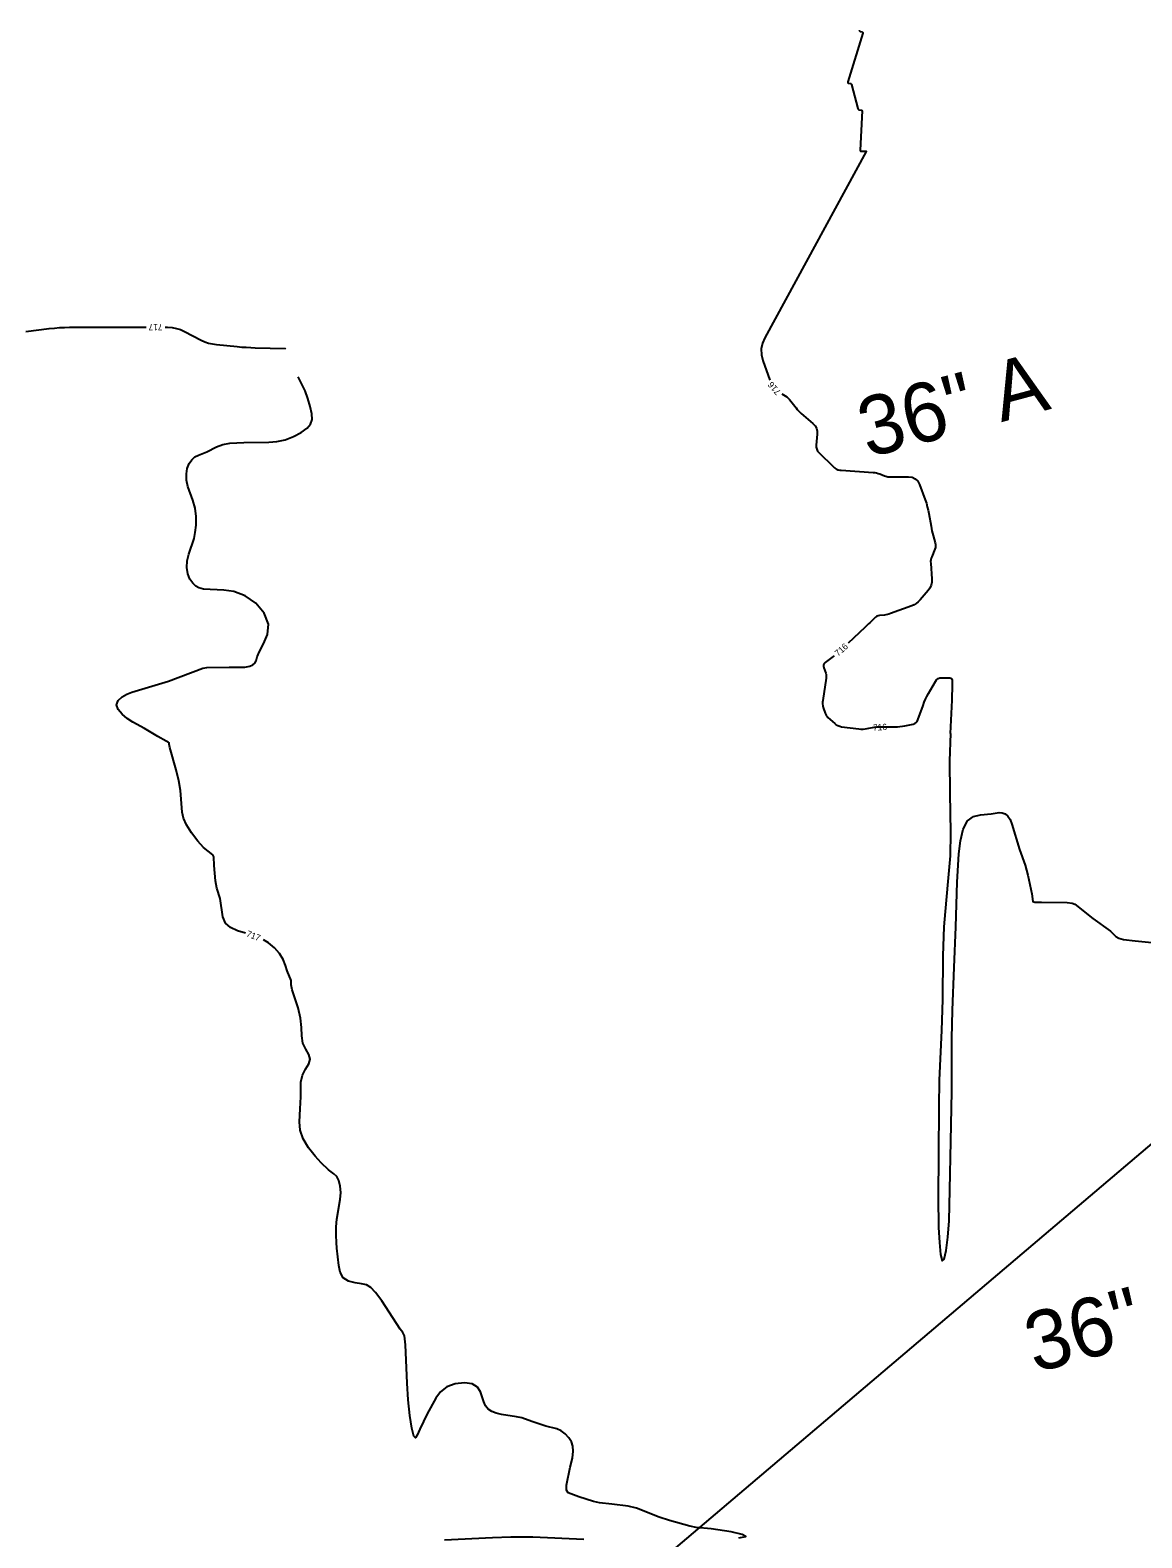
# Model space of a CAD drawing. Extents: x -361782338 to 28259792, y -263199453 to 8342113.
# Drawn here: x 1402889 to 1403593, y 576397 to 577352 of the extents above; entities that cross this region are included whole.
import ezdxf

# ---------------------------------------------------------------- set-up
doc = ezdxf.new("R2010")
doc.units = 0
for name, color, linetype in [('DT_X_Contour_Minor', 7, 'Continuous'), ('Level 19', 7, 'Continuous'), ('Level 40', 7, 'Continuous')]:
    doc.layers.add(name, color=color, linetype=linetype)

msp = doc.modelspace()

# ---------------------------------------------------------------- linework, layer by layer
at = {"layer": 'DT_X_Contour_Minor'}
for points in [[(1403413.63, 577351.77), (1403413.63, 577351.58), (1403413.74, 577351.3), (1403413.95, 577351.09), (1403414.28, 577350.95), (1403415.52, 577350.62), (1403415.74, 577350.53), (1403415.88, 577350.38), (1403415.93, 577350.19), (1403415.89, 577349.95), (1403406.42, 577318.97), (1403406.37, 577318.66), (1403406.44, 577318.41), (1403406.63, 577318.25), (1403406.94, 577318.16), (1403408.15, 577317.99), (1403408.38, 577317.93), (1403408.57, 577317.81), (1403408.7, 577317.64), (1403408.79, 577317.42), (1403412.77, 577302.05), (1403412.9, 577301.73), (1403413.1, 577301.49), (1403413.36, 577301.34), (1403413.7, 577301.27), (1403414.91, 577301.18), (1403415.13, 577301.13), (1403415.29, 577301.02), (1403415.38, 577300.85), (1403415.4, 577300.62), (1403414.2, 577275.76), (1403414.23, 577275.45), (1403414.35, 577275.23), (1403414.56, 577275.11), (1403414.87, 577275.07), (1403416.02, 577275.1), (1403416.26, 577275.1), (1403416.51, 577275.11), (1403416.76, 577275.11), (1403417, 577275.12), (1403417.85, 577275.14), (1403418, 577275.12), (1403418.08, 577275.06), (1403418.09, 577274.97), (1403418.04, 577274.83), (1403353.81, 577156.98), (1403352.31, 577153.45), (1403351.62, 577149.86), (1403351.74, 577146.21), (1403352.66, 577142.49), (1403357.04, 577130.14)], [(1402885.75, 577160.88), (1402900.65, 577162.77), (1402903.85, 577163.12), (1402907.05, 577163.38), (1402910.26, 577163.53), (1402913.48, 577163.58), (1402926.3, 577163.58), (1402929.04, 577163.58), (1402931.79, 577163.58), (1402934.54, 577163.59), (1402937.29, 577163.59), (1402950.77, 577163.59), (1402953.66, 577163.59), (1402956.54, 577163.59), (1402959.43, 577163.59), (1402961.98, 577163.59)], [(1402973.98, 577163.58), (1402975.6, 577163.58), (1402978.4, 577163.41), (1402981.13, 577162.92), (1402983.78, 577162.1), (1402986.34, 577160.96), (1402996.88, 577155.49), (1402999.18, 577154.44), (1403001.54, 577153.61), (1403003.97, 577153.02), (1403006.46, 577152.65), (1403019.67, 577151.34), (1403022.5, 577151.09), (1403025.34, 577150.89), (1403028.18, 577150.74), (1403031.02, 577150.63), (1403050, 577150.13), (1403050.02, 577150.13), (1403050.05, 577150.12), (1403050.07, 577150.11), (1403050.08, 577150.09), (1403050.16, 577150)], [(1402976.96, 576897.41), (1402976.52, 576899.58), (1402976.51, 576900.35), (1402976, 576900.85), (1402974.66, 576901.47), (1402969.42, 576904.51), (1402960.98, 576909.47), (1402953.44, 576913.59), (1402950.02, 576915.82), (1402946.77, 576918.53), (1402944.27, 576921.53), (1402943.28, 576924.5), (1402944.26, 576927.18), (1402946.7, 576929.44), (1402949.81, 576931.21), (1402952.96, 576932.46), (1402976.2, 576939.43), (1402997.91, 576947.79), (1403000.35, 576948.2), (1403014.58, 576948.27), (1403024.56, 576948.43), (1403027.66, 576949.04), (1403029.49, 576949.71), (1403030.91, 576950.77), (1403031.62, 576952.39), (1403032.27, 576954.8), (1403033.71, 576958.32), (1403036.35, 576963.13), (1403038.85, 576969), (1403039.39, 576975.59), (1403036.67, 576982.47), (1403031.36, 576988.78), (1403024.62, 576993.58), (1403017.58, 576996.19), (1403011.09, 576997.16), (1402998.27, 576997.7), (1402995.43, 576998.62), (1402993.55, 576999.68), (1402991.58, 577001.45), (1402989.73, 577004.11), (1402988.3, 577007.52), (1402987.65, 577011.48), (1402987.98, 577015.76), (1402989, 577019.98), (1402992.37, 577029.91), (1402993.11, 577033.53), (1402993.6, 577038.25), (1402993.63, 577043.65), (1402993, 577049.06), (1402991.6, 577053.99), (1402988.37, 577062.71), (1402987.57, 577066.82), (1402987.48, 577070.7), (1402988.05, 577074.23), (1402989.19, 577077.26), (1402990.81, 577079.71), (1402992.79, 577081.5), (1402995.06, 577082.67), (1403000.31, 577084.63), (1403006.63, 577087.92), (1403010.49, 577089.36), (1403014.92, 577090.17), (1403023.93, 577090.56), (1403039.74, 577090.92), (1403044.76, 577091.33), (1403050.07, 577092.4), (1403055.36, 577094.36), (1403060.15, 577096.91), (1403063.88, 577099.63), (1403066.13, 577102.27), (1403067.03, 577105.16), (1403066.86, 577108.79), (1403065.89, 577113.44), (1403064.4, 577118.53), (1403062.68, 577123.25), (1403059.15, 577130.48), (1403058.26, 577132.17)], [(1403364.66, 577121.41), (1403366.75, 577120.13), (1403367.75, 577119.44), (1403368.68, 577118.67), (1403369.54, 577117.81), (1403370.31, 577116.86), (1403373.59, 577112.48), (1403374.32, 577111.56), (1403375.09, 577110.69), (1403375.92, 577109.86), (1403376.79, 577109.08), (1403384.3, 577102.7), (1403385.67, 577101.25), (1403386.59, 577099.62), (1403387.06, 577097.81), (1403387.07, 577095.82), (1403386.38, 577089), (1403386.38, 577087.6), (1403386.69, 577086.3), (1403387.29, 577085.12), (1403388.2, 577084.04), (1403397.23, 577075.35), (1403397.42, 577075.17), (1403397.61, 577075), (1403397.81, 577074.84), (1403398.02, 577074.69), (1403398.7, 577074.19), (1403398.85, 577074.09), (1403398.99, 577073.98), (1403399.14, 577073.88), (1403399.29, 577073.77), (1403399.79, 577073.41), (1403399.9, 577073.34), (1403400.01, 577073.29), (1403400.14, 577073.25), (1403400.27, 577073.23), (1403401.27, 577073.14), (1403401.49, 577073.12), (1403401.71, 577073.1), (1403401.92, 577073.08), (1403402.14, 577073.07), (1403422.57, 577071.62), (1403423.6, 577071.51), (1403424.62, 577071.32), (1403425.61, 577071.05), (1403426.59, 577070.7), (1403429.74, 577069.44), (1403430.43, 577069.2), (1403431.12, 577069.03), (1403431.83, 577068.93), (1403432.56, 577068.9), (1403444.76, 577068.9), (1403447.16, 577068.59), (1403449.14, 577067.67), (1403450.69, 577066.14), (1403451.81, 577063.99), (1403455.42, 577054.2), (1403456.15, 577052.09), (1403456.77, 577049.95), (1403457.3, 577047.79), (1403457.73, 577045.6), (1403459.1, 577037.58), (1403459.38, 577036.1), (1403459.69, 577034.64), (1403460.04, 577033.18), (1403460.44, 577031.74), (1403461.79, 577027.03), (1403461.99, 577026.02), (1403462.02, 577025.03), (1403461.88, 577024.04), (1403461.56, 577023.07), (1403459.58, 577018.3), (1403459.22, 577017.27), (1403458.99, 577016.22), (1403458.88, 577015.15), (1403458.9, 577014.06), (1403459.67, 577004.22), (1403459.64, 577002.17), (1403459.23, 577000.25), (1403458.43, 576998.46), (1403457.24, 576996.79), (1403452.18, 576990.88), (1403451.03, 576989.7), (1403449.76, 576988.69), (1403448.38, 576987.86), (1403446.87, 576987.19), (1403433.41, 576982.23), (1403432.47, 576981.92), (1403431.53, 576981.67), (1403430.57, 576981.47), (1403429.59, 576981.34), (1403426.38, 576981), (1403425.72, 576980.88), (1403425.1, 576980.65), (1403424.52, 576980.33), (1403424, 576979.91), (1403420.33, 576976.47), (1403419.54, 576975.74), (1403418.76, 576975), (1403417.98, 576974.26), (1403417.19, 576973.52)], [(1403417.19, 576973.52), (1403406.63, 576963.53)], [(1403397.69, 576955.53), (1403397.11, 576955.09), (1403392.16, 576951.36), (1403391.42, 576950.63), (1403391.01, 576949.82), (1403390.92, 576948.9), (1403391.15, 576947.9), (1403392.43, 576944.45), (1403392.65, 576943.71), (1403392.78, 576942.95), (1403392.8, 576942.19), (1403392.73, 576941.42), (1403390.51, 576927.31), (1403390.39, 576926.16), (1403390.42, 576925.03), (1403390.58, 576923.9), (1403390.88, 576922.78), (1403392.09, 576919.16), (1403392.39, 576918.41), (1403392.78, 576917.72), (1403393.26, 576917.09), (1403393.82, 576916.51), (1403398.15, 576912.61), (1403399.12, 576911.86), (1403400.16, 576911.28), (1403401.28, 576910.87), (1403402.48, 576910.63), (1403413.38, 576909.27), (1403414.72, 576909.15), (1403416.07, 576909.14), (1403417.41, 576909.23), (1403418.75, 576909.43), (1403423.13, 576910.25), (1403424.07, 576910.4), (1403425.01, 576910.51), (1403425.96, 576910.57), (1403426.91, 576910.6), (1403436.17, 576910.6), (1403437.78, 576910.64), (1403439.39, 576910.76), (1403440.99, 576910.96), (1403442.59, 576911.25), (1403447.78, 576912.31), (1403448.8, 576912.64), (1403449.64, 576913.18), (1403450.29, 576913.94), (1403450.76, 576914.9), (1403454.03, 576924.11), (1403454.78, 576926.06), (1403455.6, 576927.97), (1403456.52, 576929.85), (1403457.52, 576931.68), (1403461.88, 576939.3), (1403462.65, 576940.34), (1403463.59, 576941.08), (1403464.71, 576941.5), (1403466.01, 576941.62), (1403471.05, 576941.48), (1403471.66, 576941.38), (1403472.1, 576941.11), (1403472.37, 576940.67), (1403472.47, 576940.05), (1403472.5, 576937.78), (1403472.5, 576937.29), (1403472.5, 576936.8), (1403472.49, 576936.31), (1403472.48, 576935.83), (1403472.3, 576928.98), (1403472.26, 576927.52), (1403472.21, 576926.05), (1403472.15, 576924.59), (1403472.08, 576923.12), (1403471.27, 576906.28)], [(1403471.36, 576906.28), (1403470.81, 576889.06), (1403470.92, 576868.53), (1403471.51, 576843.59), (1403471.14, 576828.74), (1403469.85, 576812.67), (1403468.01, 576793.64), (1403467.26, 576783.87), (1403466.63, 576765.44), (1403466.28, 576737.76), (1403465.66, 576718.27), (1403464.21, 576686.75), (1403463.98, 576669.86), (1403463.87, 576639.57), (1403463.56, 576612.72), (1403463.84, 576593.54), (1403464.38, 576584.02), (1403465.21, 576576.31), (1403466.27, 576572.32), (1403467.51, 576573.43), (1403468.75, 576578.88), (1403469.8, 576587.38), (1403470.5, 576597.58), (1403471.11, 576617.39), (1403471.7, 576648.03), (1403472.31, 576679.59), (1403472.25, 576713.21), (1403472.65, 576731.11), (1403473.81, 576758.01), (1403474.8, 576783.88), (1403475.75, 576812.08), (1403476.75, 576830.02), (1403477.73, 576838.4), (1403479.41, 576845.64), (1403482.15, 576850.93), (1403486.1, 576853.78), (1403490.51, 576854.87), (1403497.12, 576855.48), (1403502.29, 576856.33), (1403504.21, 576856.12), (1403506.08, 576855.38), (1403507.74, 576853.94), (1403509.17, 576851.78), (1403510.38, 576848.89), (1403515.17, 576832.92), (1403518.73, 576822.97), (1403520.5, 576816.52), (1403523.02, 576804.78), (1403523.66, 576799.92), (1403524.86, 576799.56), (1403529, 576799.4), (1403545.4, 576799.18), (1403548.46, 576798.91), (1403550.15, 576798.25), (1403561.55, 576789.08), (1403572.87, 576781.13), (1403576.25, 576777.74), (1403578.07, 576776.66), (1403580.95, 576775.91), (1403588.46, 576775), (1403598.89, 576774.01)], [(1403025.01, 576779.8), (1403019.93, 576781.43), (1403015.47, 576783.46), (1403012.23, 576786.29), (1403010.59, 576790.14), (1403008.83, 576801.72), (1403006.71, 576808.37), (1403005.87, 576813.07), (1403004.98, 576822.76), (1403004.75, 576828.2), (1403004.27, 576829.5), (1402998.39, 576834.04), (1402994.63, 576838.17), (1402990.69, 576843.3), (1402987.43, 576848.39), (1402985.53, 576852.68), (1402984.69, 576856.48), (1402983.79, 576870.24), (1402982.78, 576876.41), (1402981.04, 576883.31), (1402976.96, 576897.41)], [(1403094.3, 576558.38), (1403090.11, 576559.43), (1403086.71, 576561.55), (1403084.78, 576565.06), (1403083.97, 576569.36), (1403082.86, 576580.3), (1403082.52, 576584), (1403082.35, 576588.64), (1403082.43, 576593.8), (1403082.81, 576598.81), (1403084.96, 576611.24), (1403085.19, 576615.53), (1403084.91, 576619.7), (1403084.07, 576623.23), (1403082.66, 576625.72), (1403080.92, 576627.4), (1403077.54, 576629.87), (1403072.89, 576634.42), (1403069.02, 576638.69), (1403064.84, 576643.98), (1403061.43, 576649.66), (1403059.6, 576655.18), (1403059.05, 576660.3), (1403059.52, 576668.68), (1403059.92, 576676.18), (1403059.98, 576685.42), (1403060.91, 576689.9), (1403062.87, 576693.71), (1403064.96, 576697), (1403065.94, 576700.03), (1403065.02, 576703.07), (1403063.04, 576706.39), (1403061.25, 576710.22), (1403060.54, 576714.76), (1403060.36, 576720.05), (1403059.8, 576726.06), (1403058.23, 576732.63), (1403054.54, 576744.03), (1403053.87, 576747.23), (1403053.88, 576749.87), (1403051.29, 576756.06), (1403050.28, 576759.38), (1403048.73, 576763.12), (1403046.4, 576766.97), (1403043.29, 576770.63), (1403039.46, 576773.8), (1403036.24, 576775.57)], [(1403337.29, 576396.86), (1403341.91, 576397.66), (1403339.47, 576399.05), (1403332.56, 576400.66), (1403319.86, 576402.7), (1403310.4, 576403.38), (1403306.34, 576404.27), (1403293.52, 576407.87), (1403286.97, 576410.09), (1403272.56, 576415.73), (1403267.31, 576416.91), (1403256.86, 576418.26), (1403249.18, 576419.09), (1403245.29, 576419.9), (1403235.94, 576422.8), (1403229.34, 576425.45), (1403228.14, 576427.11), (1403228.18, 576430.23), (1403230.65, 576441.55), (1403231.92, 576447.34), (1403232.49, 576451.7), (1403232.28, 576454.92), (1403231.31, 576457.63), (1403229.61, 576460.32), (1403227.38, 576462.79), (1403224.82, 576464.7), (1403222.06, 576465.84), (1403215.16, 576467.53), (1403206.17, 576470.62), (1403200.03, 576472.8), (1403196.54, 576473.43), (1403187.09, 576475.07), (1403183.77, 576475.84), (1403180.84, 576476.86), (1403178.52, 576478.35), (1403176.9, 576480.46), (1403175.76, 576483.1), (1403173.68, 576489.39), (1403171.79, 576492.32), (1403168.53, 576494.38), (1403163.56, 576495.09), (1403157.79, 576494.44), (1403152.43, 576492.52), (1403148.4, 576489.43), (1403145.38, 576485.39), (1403140.03, 576475.53), (1403135.24, 576465.67), (1403133.73, 576461.93), (1403132.64, 576460.14), (1403131.6, 576461.39), (1403130.35, 576466.41), (1403129.06, 576474.42), (1403127.97, 576484.27), (1403127.28, 576494.81), (1403126.28, 576519.08), (1403125.52, 576524.83), (1403124.58, 576526.91), (1403122.93, 576529.14), (1403111.18, 576547.04), (1403107.33, 576552.26), (1403104.26, 576555.47), (1403101.5, 576557.07), (1403098.32, 576557.8), (1403094.3, 576558.38)], [(1403151.04, 576395.55), (1403181.41, 576397.11), (1403193.03, 576397.61), (1403206.88, 576397.52), (1403239.2, 576396.1)]]:
    msp.add_lwpolyline(points, dxfattribs=at)
at = {"layer": 'Level 40'}
msp.add_line((1403841.61, 576852.64), (1403205.9, 576313.06), dxfattribs=at)

# ---------------------------------------------------------------- texts
at = {"layer": 'Level 19'}
for s, rotation, p in [('717', 179.97034, (1402972.36, 577165.58)), ('716', 131.11379, (1403364.24, 577122.82)), ('716', 41.80838, (1403400.26, 576954.94)), ('716', 3.99352, (1403422.46, 576907.95)), ('717', 338.67535, (1403025.09, 576777.97))]:
    msp.add_text(s, height=4, rotation=rotation, dxfattribs=at).set_placement(p)
at = {"layer": 'Level 40'}
for p in [(1403419.06, 577080.76), (1403524.79, 576501.27)]:
    msp.add_text('36" A', height=37.5, rotation=15, dxfattribs=at).set_placement(p)

doc.saveas('drawing.dxf')
